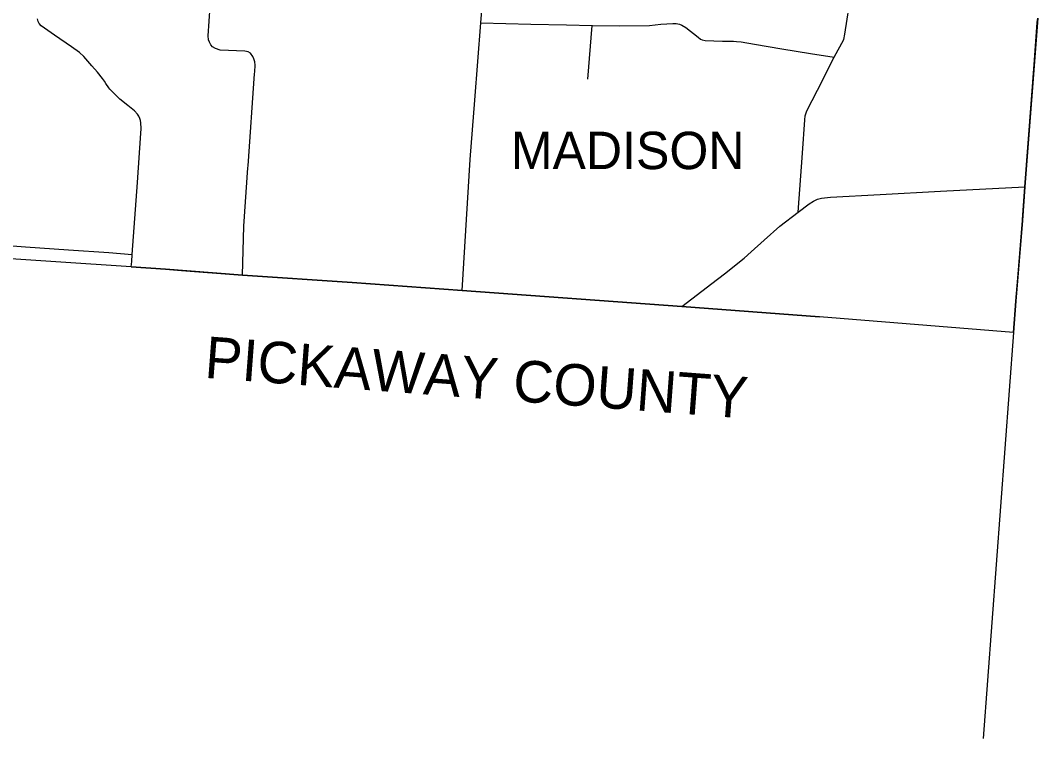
# Model space of a CAD drawing. Extents: x 1755200 to 1902939, y 644115 to 788070.
# Drawn here: x 1853497 to 1877958, y 644115 to 661397 of the extents above; entities that cross this region are included whole.
import ezdxf

# ---------------------------------------------------------------- set-up
doc = ezdxf.new("R2010")
doc.units = 0
for name, color, linetype in [('GM_X_Adjacent_County', 7, 'Continuous'), ('GM_X_Adjacent_County_Text', 7, 'Continuous'), ('GM_X_County', 7, 'Continuous'), ('GM_X_County_Road', 7, 'Continuous'), ('GM_X_State_Route', 7, 'Continuous'), ('GM_X_Township_Road', 7, 'Continuous'), ('GM_X_Township_Text', 7, 'Continuous')]:
    doc.layers.add(name, color=color, linetype=linetype)

msp = doc.modelspace()

# ---------------------------------------------------------------- linework, layer by layer
at = {"layer": 'GM_X_Adjacent_County'}
msp.add_line((1877380, 653885), (1876647, 644115), dxfattribs=at)
at = {"layer": 'GM_X_County'}
msp.add_lwpolyline([(1877958, 661450), (1877649, 657393), (1877591, 656580), (1877433, 654641), (1877380, 653888), (1872712, 654264), (1869398, 654514), (1864124, 654894), (1861474, 655088), (1858836, 655268), (1856984, 655410), (1856164, 655463), (1848544, 655971)], dxfattribs=at)
at = {"layer": 'GM_X_County_Road'}
for points in [[(1864569, 661334), (1864755, 663649), (1864875, 665092), (1864872, 665174), (1864827, 665345), (1864754, 665527), (1864756, 665581)], [(1872662, 659716), (1873068, 660509), (1873300, 660936), (1873325, 661064), (1873471, 662054), (1873523, 662158), (1873562, 662223)], [(1856164, 655463), (1856176, 655593), (1856187, 655765), (1856312, 657499), (1856361, 658208), (1856403, 658797), (1856396, 658931), (1856383, 658986), (1856370, 659032), (1856344, 659088), (1856313, 659140), (1856245, 659220), (1856085, 659350), (1855892, 659499), (1855806, 659583), (1855651, 659742), (1855627, 659771), (1855555, 659874), (1855517, 659937), (1855473, 659999), (1855354, 660151), (1855218, 660305), (1855021, 660524), (1854916, 660624), (1854729, 660761), (1854321, 661040), (1853995, 661268), (1853951, 661320), (1853925, 661369), (1853910, 661437)], [(1864124, 654894), (1864310, 658049), (1864422, 659478), (1864569, 661334)], [(1872302, 658199), (1872358, 659001), (1872365, 659097), (1872407, 659218), (1872662, 659716)], [(1869398, 654514), (1870125, 655063), (1870427, 655297), (1870901, 655676), (1871071, 655826), (1871383, 656105), (1871761, 656444), (1872202, 656780), (1872302, 658199)], [(1872202, 656780), (1872465, 656982), (1872570, 657045), (1872667, 657091), (1872757, 657116), (1872975, 657143), (1874171, 657208), (1875618, 657288), (1877649, 657393)], [(1856164, 655463), (1856984, 655410), (1857372, 655380)], [(1857372, 655380), (1858836, 655268), (1861474, 655088), (1864124, 654894), (1869398, 654514)]]:
    msp.add_lwpolyline(points, dxfattribs=at)
at = {"layer": 'GM_X_State_Route'}
for points in [[(1877949, 661344), (1877958, 661450)], [(1877880, 660436), (1877949, 661344)], [(1877593, 656608), (1877649, 657393), (1877880, 660436)], [(1877478, 655196), (1877591, 656580), (1877593, 656608)], [(1877380, 653888), (1877433, 654641), (1877478, 655196)]]:
    msp.add_lwpolyline(points, dxfattribs=at)
at = {"layer": 'GM_X_Township_Road'}
for points in [[(1859131, 660161), (1859141, 660315), (1859136, 660397), (1859113, 660471), (1859087, 660526), (1859032, 660604), (1858972, 660643), (1858892, 660654), (1858303, 660680), (1858187, 660721), (1858119, 660762), (1858080, 660806), (1858046, 660868), (1858022, 660927), (1858015, 661025), (1858084, 662089)], [(1864569, 661334), (1865771, 661306), (1866628, 661287), (1867244, 661275), (1867254, 661275), (1867914, 661265), (1868625, 661276), (1868895, 661302), (1869189, 661319), (1869267, 661318), (1869343, 661305), (1869405, 661280), (1869496, 661226), (1869796, 660991), (1869852, 660945), (1869893, 660924), (1869961, 660915), (1870383, 660898), (1870647, 660894), (1870717, 660887), (1870831, 660879), (1871146, 660826), (1871808, 660712), (1872499, 660597), (1873068, 660509)], [(1867144, 659985), (1867244, 661275)], [(1858973, 657900), (1859127, 660110), (1859131, 660161)], [(1858836, 655268), (1858871, 656441), (1858969, 657849), (1858973, 657900)], [(1850858, 656754), (1850857, 656750), (1850863, 656668), (1850906, 656518), (1850979, 656409), (1851122, 656261), (1851262, 656206), (1851416, 656169), (1851980, 656111), (1852783, 656012), (1853619, 655950), (1854656, 655877), (1855625, 655810), (1856187, 655765)], [(1869398, 654514), (1872712, 654264)]]:
    msp.add_lwpolyline(points, dxfattribs=at)

# ---------------------------------------------------------------- texts
at = {"layer": 'GM_X_Adjacent_County_Text'}
msp.add_text('PICKAWAY COUNTY', height=1000, rotation=355.6868, dxfattribs=at).set_placement((1857908, 652798))
at = {"layer": 'GM_X_Township_Text'}
msp.add_text('MADISON', height=900, rotation=0, dxfattribs=at).set_placement((1865291, 657817))

doc.saveas('drawing.dxf')
